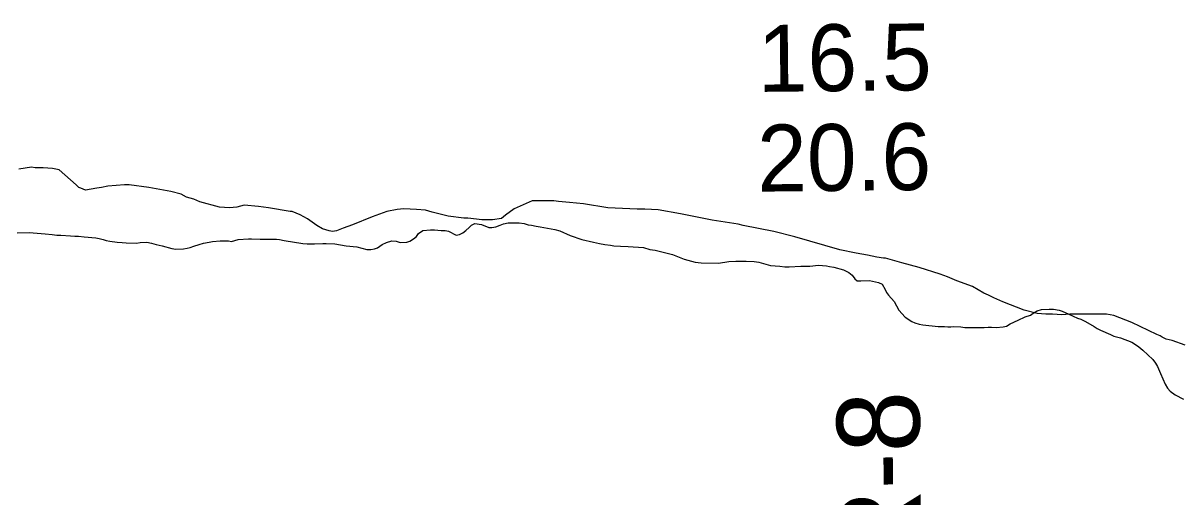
# Model space of a CAD drawing. Extents: x 3192927 to 3230760, y 831141 to 856475.
# Drawn here: x 3197765 to 3198923, y 851759 to 852234 of the extents above; entities that cross this region are included whole.
import ezdxf

# ---------------------------------------------------------------- set-up
doc = ezdxf.new("R2010")
doc.units = 0
for name, color, linetype in [('V-RIVR-RANG', 7, 'Continuous'), ('V-RIVR-RANG-IDEN', 7, 'Continuous'), ('V-SITE-VEGE', 7, 'Continuous'), ('V-TOPO-SHOR', 7, 'Continuous')]:
    doc.layers.add(name, color=color, linetype=linetype)

msp = doc.modelspace()

# ---------------------------------------------------------------- linework, layer by layer
at = {"layer": 'V-SITE-VEGE'}
for p, q in [((3197773.9, 852090), (3197761.1, 852088)), ((3197777.3, 852089.3), (3197773.9, 852090)), ((3197785.3, 852089.3), (3197777.3, 852089.3)), ((3197794.8, 852088.6), (3197785.3, 852089.3)), ((3197801.5, 852087.2), (3197794.8, 852088.6)), ((3197818.4, 852072.4), (3197801.5, 852087.2)), ((3197821.1, 852069.7), (3197818.4, 852072.4)), ((3197823.1, 852069), (3197821.1, 852069.7)), ((3197827.8, 852067), (3197823.1, 852069)), ((3197839.3, 852069), (3197827.8, 852067)), ((3197844, 852069.6), (3197839.3, 852069)), ((3197850.1, 852071), (3197844, 852069.6)), ((3197866.9, 852072.3), (3197850.1, 852071)), ((3197871.7, 852072.3), (3197866.9, 852072.3)), ((3197891.2, 852069.6), (3197871.7, 852072.3)), ((3197913.5, 852065.5), (3197891.2, 852069.6)), ((3197923.6, 852062.8), (3197913.5, 852065.5)), ((3197929, 852060), (3197923.6, 852062.8)), ((3197936.4, 852058), (3197929, 852060)), ((3197942.4, 852055.3), (3197936.4, 852058)), ((3197962, 852049.9), (3197942.4, 852055.3)), ((3197972.1, 852049.2), (3197962, 852049.9)), ((3197979.5, 852049.8), (3197972.1, 852049.2)), ((3197987, 852051.9), (3197979.5, 852049.8)), ((3198001.1, 852050.5), (3197987, 852051.9)), ((3198011.2, 852049.1), (3198001.1, 852050.5)), ((3198275.6, 852056.1), (3198257.4, 852048.1)), ((3198297.2, 852056.1), (3198275.6, 852056.1)), ((3198301.9, 852055.4), (3198297.2, 852056.1)), ((3198312.7, 852054.7), (3198301.9, 852055.4)), ((3198326.9, 852053.3), (3198312.7, 852054.7)), ((3198351.2, 852049.3), (3198326.9, 852053.3)), ((3198380.8, 852047.9), (3198351.2, 852049.3)), ((3198032.8, 852045.7), (3198011.2, 852049.1)), ((3198034.8, 852045.7), (3198032.8, 852045.7)), ((3198042.9, 852042.3), (3198034.8, 852045.7)), ((3198050.3, 852038.3), (3198042.9, 852042.3)), ((3198059.8, 852031.5), (3198050.3, 852038.3)), ((3198115.1, 852040.2), (3198095.5, 852032.1)), ((3198129.9, 852045.6), (3198115.1, 852040.2)), ((3198140.1, 852047.6), (3198129.9, 852045.6)), ((3198146.8, 852048.2), (3198140.1, 852047.6)), ((3198159.6, 852047.5), (3198146.8, 852048.2)), ((3198168.4, 852046.8), (3198159.6, 852047.5)), ((3198175.1, 852044.8), (3198168.4, 852046.8)), ((3198191.3, 852040.7), (3198175.1, 852044.8)), ((3198206.8, 852038.7), (3198191.3, 852040.7)), ((3198210.9, 852038.7), (3198206.8, 852038.7)), ((3198219.6, 852038), (3198210.9, 852038.7)), ((3198225, 852037.3), (3198219.6, 852038)), ((3198244.6, 852038.6), (3198235.8, 852037.3)), ((3198248.6, 852042), (3198244.6, 852038.6)), ((3198257.4, 852048.1), (3198248.6, 852042)), ((3198388.3, 852047.8), (3198380.8, 852047.9)), ((3198401.7, 852047.2), (3198388.3, 852047.8)), ((3198424, 852043.1), (3198401.7, 852047.2)), ((3198437.5, 852040.4), (3198424, 852043.1)), ((3198455.7, 852036.9), (3198437.5, 852040.4)), ((3198065.2, 852028.1), (3198059.8, 852031.5)), ((3198071.9, 852026.1), (3198065.2, 852028.1)), ((3198075.3, 852025.4), (3198071.9, 852026.1)), ((3198079.3, 852026.1), (3198075.3, 852025.4)), ((3198086.1, 852028.8), (3198079.3, 852026.1)), ((3198095.5, 852032.1), (3198086.1, 852028.8)), ((3198235.8, 852037.3), (3198225, 852037.3)), ((3198482, 852032.9), (3198455.7, 852036.9)), ((3198486.7, 852031.5), (3198482, 852032.9)), ((3198517.7, 852025.4), (3198486.7, 852031.5)), ((3198538.6, 852020), (3198517.7, 852025.4)), ((3198583.8, 852007.1), (3198538.6, 852020)), ((3198600, 852003.7), (3198583.8, 852007.1)), ((3198611.4, 852001.6), (3198600, 852003.7)), ((3198620.9, 851999.6), (3198611.4, 852001.6)), ((3198627.6, 851998.9), (3198620.9, 851999.6)), ((3198629.6, 851998.9), (3198627.6, 851998.9)), ((3198645.8, 851994.2), (3198629.6, 851998.9)), ((3198663.3, 851989.4), (3198645.8, 851994.2)), ((3198684.2, 851982.6), (3198663.3, 851989.4)), ((3198691.7, 851979.9), (3198684.2, 851982.6)), ((3198701.1, 851975.9), (3198691.7, 851979.9)), ((3198716.6, 851970.4), (3198701.1, 851975.9)), ((3198728, 851963.7), (3198716.6, 851970.4)), ((3198732.8, 851961.6), (3198728, 851963.7)), ((3198738.2, 851958.9), (3198732.8, 851961.6)), ((3198746.9, 851954.9), (3198738.2, 851958.9)), ((3198768.5, 851946.7), (3198746.9, 851954.9)), ((3198781.3, 851943.4), (3198768.5, 851946.7)), ((3198790.1, 851942.7), (3198781.3, 851943.4)), ((3198796.8, 851942.7), (3198790.1, 851942.7)), ((3198806.2, 851942), (3198796.8, 851942.7)), ((3198814.3, 851942.6), (3198806.2, 851942)), ((3198850.8, 851942.6), (3198814.3, 851942.6)), ((3198858.2, 851941.2), (3198850.8, 851942.6)), ((3198876.4, 851934.4), (3198858.2, 851941.2)), ((3198901.3, 851922.3), (3198876.4, 851934.4)), ((3198904.7, 851920.9), (3198901.3, 851922.3)), ((3198906.7, 851919.5), (3198904.7, 851920.9)), ((3198910.8, 851917.5), (3198906.7, 851919.5)), ((3198916.8, 851916.2), (3198910.8, 851917.5)), ((3198929.6, 851911.4), (3198916.8, 851916.2))]:
    msp.add_line(p, q, dxfattribs=at)
at = {"layer": 'V-TOPO-SHOR'}
for points in [[(3198143.1, 852014.6), (3198149.9, 852014.8), (3198152.9, 852015.7), (3198156.4, 852018), (3198159.7, 852020.6), (3198161.6, 852023.4), (3198165.8, 852026.4), (3198173.5, 852027.1), (3198177.7, 852027.1), (3198184.2, 852026.4), (3198188.2, 852026.4), (3198191.5, 852025.7), (3198199.2, 852021.9), (3198202.7, 852022.4), (3198205.9, 852024), (3198209, 852026.4), (3198212.2, 852029.6), (3198214.8, 852031.7), (3198218.1, 852033.6), (3198224.6, 852032.6), (3198232.1, 852029.6), (3198235.1, 852029.6), (3198238.9, 852030.3), (3198243.3, 852031.9), (3198246.6, 852033.3), (3198251.5, 852034.2), (3198259.4, 852034.2), (3198262.5, 852034.2), (3198267.4, 852033.5), (3198271.3, 852032.3), (3198274.8, 852031.9), (3198279.5, 852030.7), (3198283.5, 852030.2), (3198298.2, 852027.6), (3198303.1, 852026), (3198313.4, 852021.5), (3198325.3, 852017.5), (3198336.9, 852014.7), (3198342.8, 852013.5), (3198348.1, 852012.6), (3198354, 852011.9), (3198357.2, 852011.2), (3198364, 852010.7), (3198371.7, 852010.5), (3198386.9, 852009.3), (3198393.2, 852007.6), (3198398.8, 852006.7), (3198416.1, 852002.4), (3198427.8, 851997.8), (3198438.7, 851994.9), (3198444.8, 851994), (3198462.1, 851993.7), (3198472.6, 851995.4), (3198479.4, 851995.8), (3198489.9, 851995.8), (3198498, 851995.3), (3198502.7, 851994.8), (3198514.4, 851991.5), (3198523.5, 851990.6), (3198528.6, 851989.9), (3198533.1, 851989.9), (3198544.5, 851990.6), (3198548.9, 851990.6), (3198553.6, 851990.8), (3198562.3, 851991.7), (3198566.5, 851991.5), (3198570.4, 851991), (3198573.5, 851990.3), (3198577.7, 851989.8), (3198587.5, 851987), (3198592.6, 851984.4), (3198596.1, 851981.8), (3198598.7, 851978.1), (3198601.2, 851976), (3198604.7, 851976), (3198613.4, 851976.4), (3198622.5, 851974.3), (3198626.2, 851972.7), (3198629.2, 851967.5), (3198630.6, 851964.5), (3198632.5, 851961.5), (3198638.1, 851955.2), (3198643, 851946.7), (3198649.3, 851939.5), (3198655.8, 851935.3), (3198658.9, 851933.9), (3198663.3, 851932.7), (3198666.8, 851931.8), (3198682.4, 851930.3), (3198688.5, 851930.3), (3198692, 851929.8), (3198695, 851929.8), (3198698.1, 851930.1), (3198705.1, 851929.8), (3198709.1, 851929.3), (3198716.3, 851929.3), (3198724.2, 851929.1), (3198728.2, 851929.3), (3198732.4, 851929.5), (3198735.7, 851929.5), (3198740.4, 851929.3)], [(3197759.4, 852024.3), (3197771.3, 852024.5), (3197787.4, 852023.3), (3197794.4, 852022.4), (3197799.3, 852021.9), (3197803.1, 852021.9), (3197812.9, 852021.2), (3197817.3, 852020.7), (3197820.8, 852020.7), (3197826.4, 852020), (3197838.3, 852019.3), (3197841.6, 852018.5), (3197845.6, 852017.6), (3197848.6, 852016.4), (3197852.3, 852015.7), (3197859.6, 852014.8), (3197864.7, 852014.5), (3197868.5, 852014.1), (3197879, 852013.8), (3197882.5, 852014.3), (3197889.2, 852014.7), (3197894.1, 852013.8), (3197898.8, 852012.4), (3197904.6, 852011.2), (3197914.5, 852008.6), (3197918.4, 852007.9), (3197926.1, 852008.1), (3197929.6, 852008.8), (3197932.7, 852009.5), (3197936.4, 852010.9), (3197941.6, 852012.5), (3197946, 852013.7), (3197951.8, 852014.9), (3197955.1, 852015.3), (3197962.8, 852016), (3197971, 852016), (3197974.2, 852015.5), (3197980.8, 852017.4), (3197991.3, 852018.3), (3197994.3, 852018.3), (3198003, 852017.8), (3198019.1, 852017.8), (3198022.4, 852017.6), (3198026.8, 852016.6), (3198045.7, 852013.3), (3198050.1, 852013.1), (3198057.2, 852013.1), (3198065.6, 852013.5), (3198069.1, 852013.5), (3198077.7, 852013), (3198089.1, 852011.1), (3198099.7, 852010.2), (3198109.9, 852007.6), (3198113.9, 852007.4), (3198117.4, 852008.1), (3198120.4, 852009.2), (3198125.1, 852012.5), (3198129.6, 852014.3), (3198134.9, 852016.2), (3198139.1, 852015.7), (3198143.1, 852014.6)], [(3198740.4, 851929.3), (3198747.4, 851929.8), (3198750.6, 851930.7), (3198754.4, 851933), (3198762.5, 851936.7), (3198769.3, 851939.8), (3198774.7, 851941.6), (3198777.5, 851943.5), (3198781.5, 851945.8), (3198785.9, 851947.2), (3198793.6, 851947.7), (3198797.8, 851947.7), (3198803.4, 851946.5), (3198806.5, 851945.5), (3198813.2, 851942.7), (3198821.9, 851938.7), (3198825.1, 851937.6), (3198830, 851935.2), (3198838.7, 851930.3), (3198841.5, 851928.4), (3198845, 851926.6), (3198854.8, 851922.1), (3198858.3, 851920.7), (3198864.8, 851918.8), (3198876.2, 851914.6), (3198880, 851912.3), (3198883.5, 851909.7), (3198887.2, 851906.6), (3198897.5, 851897.3), (3198900, 851893.5), (3198901.9, 851890), (3198905.2, 851883), (3198909.6, 851872.5), (3198911.9, 851868.5), (3198914.9, 851865.3), (3198919.6, 851861.8), (3198928, 851857.3)]]:
    msp.add_lwpolyline(points, dxfattribs=at)

# ---------------------------------------------------------------- texts
at = {"layer": 'V-RIVR-RANG'}
for s, p in [('16.5', (3198501.7, 852165.4)), ('20.6', (3198501.2, 852065.4))]:
    msp.add_text(s, height=67, rotation=0.6083, dxfattribs=at).set_placement(p)
at = {"layer": 'V-RIVR-RANG-IDEN'}
msp.add_text('R-8', height=83, rotation=90.7414, dxfattribs=at).set_placement((3198665.6, 851687.2))

doc.saveas('drawing.dxf')
